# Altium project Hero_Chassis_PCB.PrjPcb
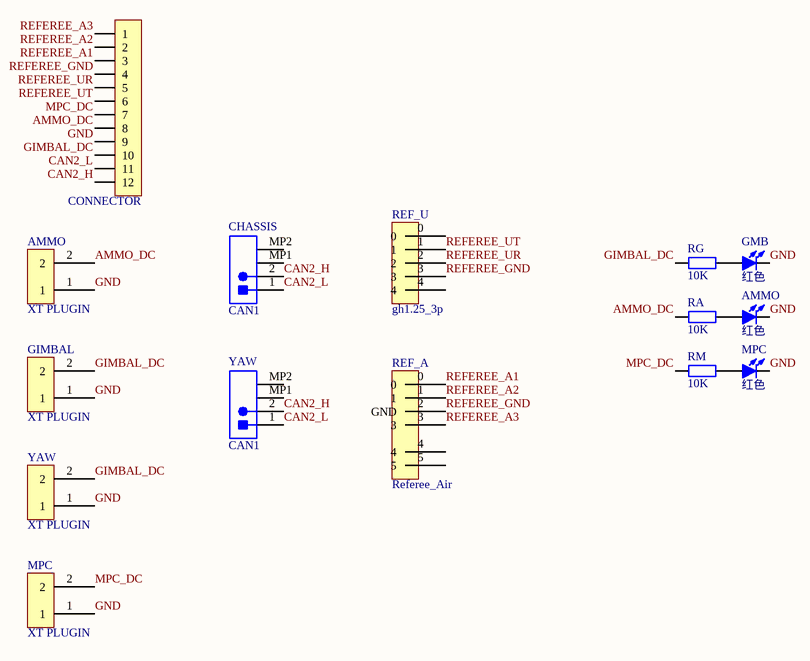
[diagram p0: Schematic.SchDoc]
1 sheet, 15 parts. Net scope: global (net labels, ports and power ports of the same name join across sheets).
Board file: Hero_Chassis_PCB.PcbDoc

## Sheet Schematic.SchDoc
size A4

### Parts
(Parts that share a designator on the sheet are numbered #1, #2 ... from top to bottom, then left to right.)
AMMO#1  XT PLUGIN  [XT30-M]
AMMO#2  红色  [LED 0805G]
CHASSIS  CAN1  [JST-BM02B-GHS-TBT_V]
CONNECTOR  HDR-1X12  [KF2EDGK5.08-LI-12P]  (value not drawn)
GIMBAL  XT PLUGIN  [XT30-M]
GMB  红色  [LED 0805G]
MPC#1  红色  [LED 0805G]
MPC#2  XT PLUGIN  [XT30-M]
RA  10K  [R 0805_L]
REF_A  Referee_Air  [M8 Connector]
REF_U  gh1.25_3p  [GH1.25-LS-3P]
RG  10K  [R 0805_L]
RM  10K  [R 0805_L]
YAW#1  CAN1  [JST-BM02B-GHS-TBT_V]
YAW#2  XT PLUGIN  [XT30-M]

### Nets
AMMO_DC: AMMO#1.2 CONNECTOR.8 RA.1
CAN2_H: CHASSIS.2 CONNECTOR.12 YAW#1.2
CAN2_L: CHASSIS.1 CONNECTOR.11 YAW#1.1
GIMBAL_DC: CONNECTOR.10 GIMBAL.2 RG.1 YAW#2.2
GND: AMMO#1.1 AMMO#2.2(K) CONNECTOR.9 GIMBAL.1 GMB.2(K) MPC#1.2(K) MPC#2.1 YAW#2.1
MPC_DC: CONNECTOR.7 MPC#2.2 RM.1
REFEREE_A1: CONNECTOR.3 REF_A.0
REFEREE_A2: CONNECTOR.2 REF_A.1
REFEREE_A3: CONNECTOR.1 REF_A.3
REFEREE_GND: CONNECTOR.4 REF_A.2(GND) REF_U.3
REFEREE_UR: CONNECTOR.5 REF_U.2
REFEREE_UT: CONNECTOR.6 REF_U.1
NetAMMO#2_1: AMMO#2.1(A) RA.2
NetGMB_1: GMB.1(A) RG.2
NetMPC#1_1: MPC#1.1(A) RM.2

Not connected (* = marked no-connect by the designer): CHASSIS MP1 MP2; REF_A 4 5; REF_U 0 4; YAW#1 MP1 MP2

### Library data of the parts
AMMO#2 GMB MPC#1 = LED-SMD: 贴片LED; 版权归属: 封装库来自淘宝 ID：黄晶宝石
CHASSIS YAW#1 = CMP-2000-05957-1: Disconnectable Crimp Style Connector, Pitch 1.25 mm, 1 x 2 Position, Height 4.05 mm, -25 to 85 degC, RoHS, Tape and Reel; Manufacturer: JST-Sales-America-Inc.; Connector Type: Header,Shrouded; Number of Positions Loaded: All; Pitch: 0.049"(1.25mm); Number of Positions: 2
CONNECTOR = Header 12: 12P接插件; 版权归属: 封装库来自淘宝卖家 ID：黄晶宝石
RA RG RM = R: 贴片电阻; 版权归属: 来自淘宝 ID：黄晶宝石; 封装库来自淘宝卖家 ID：黄晶宝石: 其他店铺购入均为盗版，不享受售后技术支持服务，请立即申请退款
